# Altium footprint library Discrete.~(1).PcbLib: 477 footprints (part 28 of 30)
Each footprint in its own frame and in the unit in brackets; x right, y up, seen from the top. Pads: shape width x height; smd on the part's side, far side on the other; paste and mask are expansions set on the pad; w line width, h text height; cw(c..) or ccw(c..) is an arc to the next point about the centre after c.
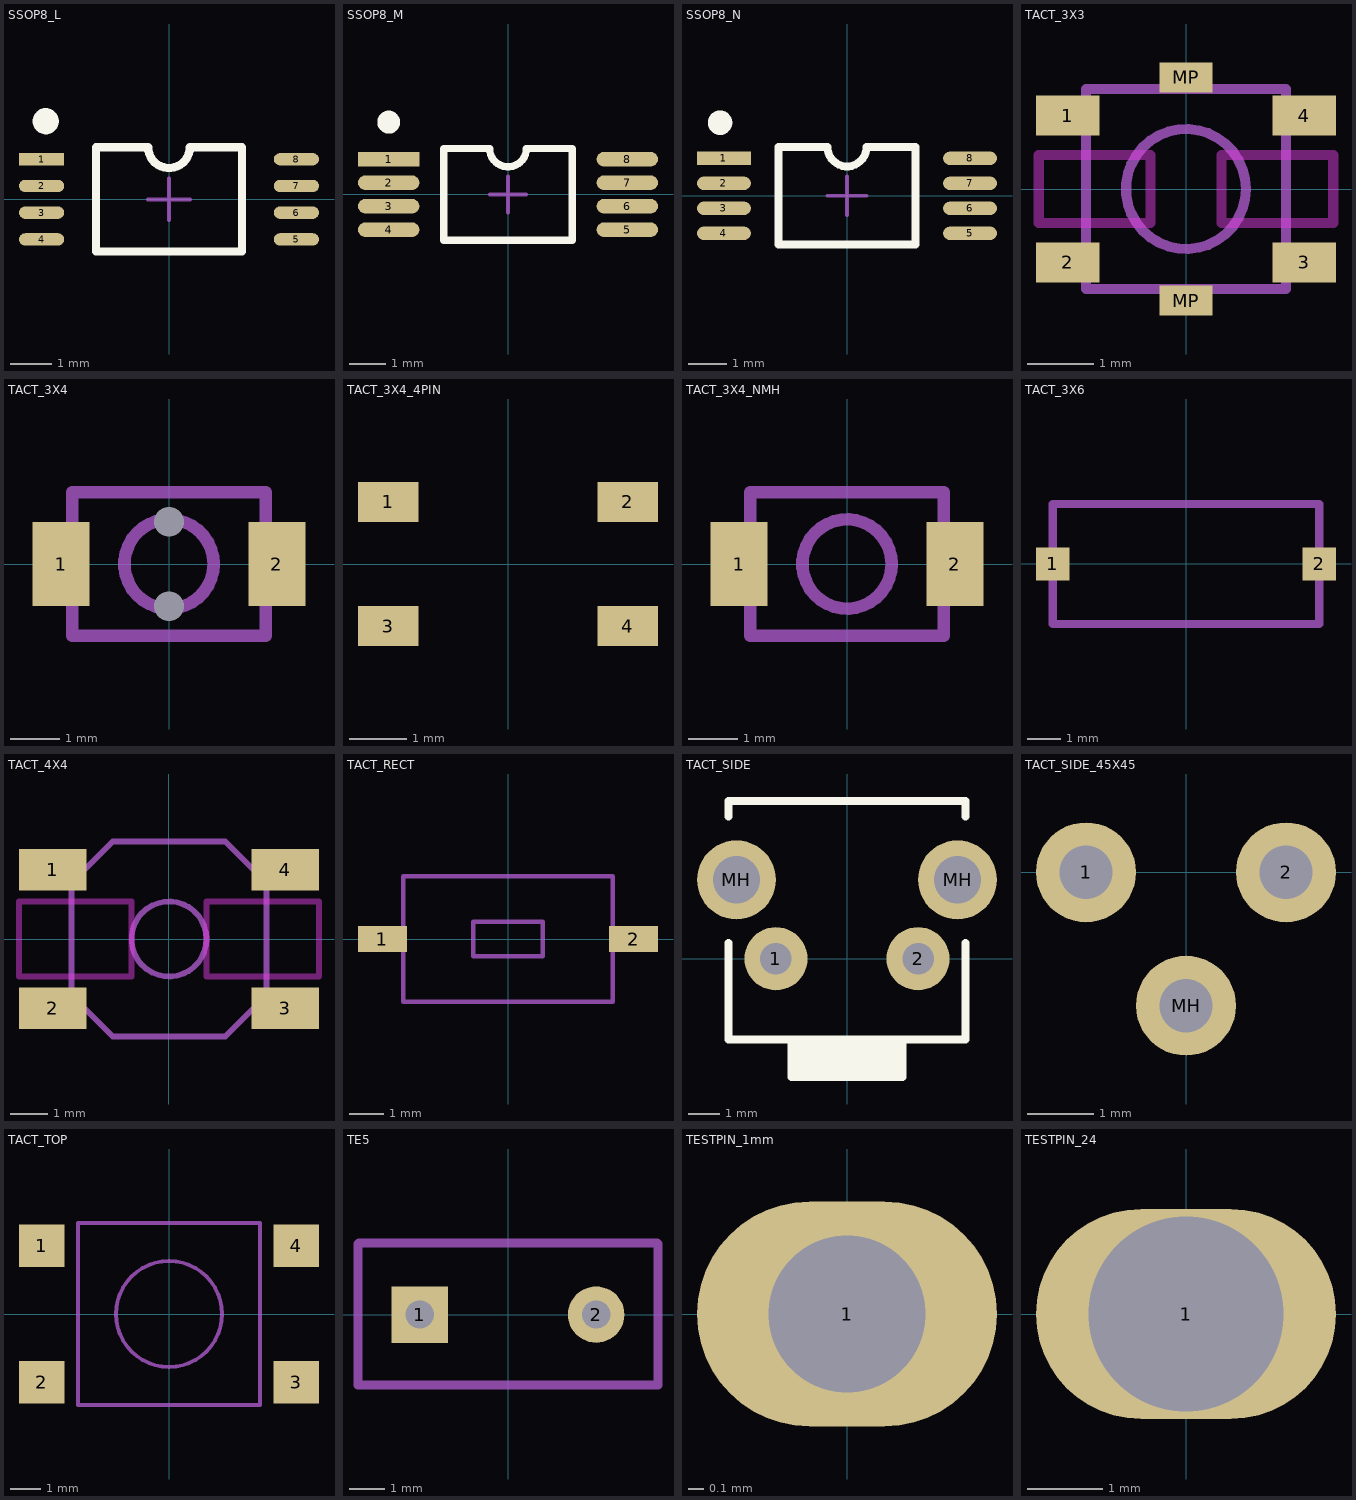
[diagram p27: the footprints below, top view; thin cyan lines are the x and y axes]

## SSOP8_L [mm] "3*6.4*1.2mm（长宽高）"
pads (8):
  rect 1.1x0.3 smd: 1(-3.1,0.975)
  oval 1.1x0.3 smd: 2(-3.1,0.325) 3(-3.1,-0.325) 4(-3.1,-0.975) 5(3.1,-0.975) 6(3.1,-0.325) 7(3.1,0.325) 8(3.1,0.975)
Top Overlay:
  circle w0.381: c-3,1.9 r0.127
  lines w0.203: -1.778,-1.27 -1.778,1.27 -0.508,1.27 ccw(c0,1.27) 0.508,1.27 1.778,1.27 1.778,-1.27 -1.778,-1.27
Mechanical 15:
  lines w0.1: -0.508,0 0.508,0 ; 0,-0.508 0,0.508
3D body "SSOP8.STEP": height 1.25, standoff -0.02, extent -3.203,-1.75 3.203,1.75

## SSOP8_M [mm] "3*6.4*1.2mm（长宽高）"
pads (8):
  rect 1.7x0.4 smd: 1(-3.3,0.975)
  oval 1.7x0.4 smd: 2(-3.3,0.325) 3(-3.3,-0.325) 4(-3.3,-0.975) 5(3.3,-0.975) 6(3.3,-0.325) 7(3.3,0.325) 8(3.3,0.975)
Top Overlay:
  circle w0.381: c-3.3,2 r0.127
  lines w0.203: -1.778,-1.27 -1.778,1.27 -0.508,1.27 ccw(c0,1.27) 0.508,1.27 1.778,1.27 1.778,-1.27 -1.778,-1.27
Mechanical 15:
  lines w0.1: -0.508,0 0.508,0 ; 0,-0.508 0,0.508
3D body "SSOP8.STEP": height 1.25, standoff -0.02, extent -3.203,-1.75 3.203,1.75

## SSOP8_N [mm] "3*6.4*1.2mm（长宽高）"
pads (8):
  rect 1.4x0.35 smd: 1(-3.2,0.975)
  oval 1.4x0.35 smd: 2(-3.2,0.325) 3(-3.2,-0.325) 4(-3.2,-0.975) 5(3.2,-0.975) 6(3.2,-0.325) 7(3.2,0.325) 8(3.2,0.975)
Top Overlay:
  circle w0.381: c-3.3,1.9 r0.127
  lines w0.203: -1.778,-1.27 1.778,-1.27 1.778,1.27 0.508,1.27 cw(c0,1.27) -0.508,1.27 -1.778,1.27 -1.778,-1.27
Mechanical 15:
  lines w0.1: -0.508,0 0.508,0 ; 0,-0.508 0,0.508
3D body "SSOP8.STEP": height 1.25, standoff -0.02, extent -3.203,-1.75 3.203,1.75

## TACT_3X3 [mm]
pads (6):
  rect 0.95x0.6 smd: 1(-1.775,1.1) 2(-1.775,-1.1) 3(1.775,-1.1) 4(1.775,1.1)
  rect 0.8x0.45 smd: MP(0,-1.675) MP(0,1.675)
Top Layer keep-out:
  lines w0.152: -2.21,-0.51 -0.533,-0.51 -0.533,0.51 -2.21,0.51 -2.21,-0.51 ; 0.533,-0.51 0.533,0.51 2.21,0.51 2.21,-0.51 0.533,-0.51
Mechanical 13:
  circle w0.152: c0,0 r0.9
  lines w0.152: -1.5,-1.5 1.5,-1.5 1.5,1.5 -1.5,1.5 -1.5,-1.5
3D body: height 1.1, standoff 0, extent -1.5,-1.5 1.5,1.5
3D body: height 1.5, standoff 0, extent -0.893,-0.898 0.9,0.898

## TACT_3X4 [mm]
pads (4):
  rect 1.15x1.7 smd: 1(-2.175,0) 2(2.175,0)
  round 0.1 hole 0.6 unplated: MH(0,-0.85) MH(0,0.85)
Mechanical 13:
  circle w0.254: c0,0 r0.9
  lines w0.254: -1.95,-1.45 1.95,-1.45 1.95,1.45 -1.95,1.45 -1.95,-1.45
3D body: height 2, standoff 1.5, extent -0.794,-0.798 0.8,0.798
3D body: height 1.5, standoff 0, extent -1.95,-1.45 1.95,1.45

## TACT_3X4_4PIN [mm]
pads (4):
  rect 1.05x0.7 smd: 1(-2.075,1.075) 2(2.075,1.075) 3(-2.075,-1.075) 4(2.075,-1.075)
3D body "SKRPADE010 v2.step": height 2.5, standoff 0, extent -2.3,-1.6 2.3,1.6

## TACT_3X4_NMH [mm]
pads (2):
  rect 1.15x1.7 smd: 1(-2.175,0) 2(2.175,0)
Mechanical 13:
  circle w0.254: c0,0 r0.9
  lines w0.254: -1.95,-1.45 -1.95,1.45 1.95,1.45 1.95,-1.45 -1.95,-1.45
3D body: height 1.5, standoff 0, extent -1.95,-1.45 1.95,1.45
3D body: height 2, standoff 1.5, extent -0.794,-0.798 0.8,0.798

## TACT_3X6 [mm]
pads (2):
  rect 1x1 smd: 1(-4,0) 2(4,0)
Mechanical 13:
  lines w0.254: -4,-1.8 4,-1.8 4,1.8 -4,1.8 -4,-1.8 ; -4,-1.8 -4,-1.8
3D body "User Library-Tact switch 1181_3.STEP": height 2.4, standoff -0.1, extent -4,-1.8 4,1.8

## TACT_4X4 [mm]
pads (4):
  rect 1.8x1.1 smd: 1(-3.1,1.85) 2(-3.1,-1.85) 3(3.1,-1.85) 4(3.1,1.85)
Top Layer keep-out:
  lines w0.152: -4,-1 -4,1 -1,1 -1,-1 -4,-1 ; 1,-1 1,1 4,1 4,-1 1,-1
Mechanical 13:
  circle w0.152: c0,0 r1
  lines w0.152: -2.6,-1.5 -2.6,1.5 -1.5,2.6 1.5,2.6 2.6,1.5 2.6,-1.5 1.5,-2.6 -1.5,-2.6 -2.6,-1.5
3D body "User Library-button1.STEP": height 1.4, standoff 0, extent -3.2,-2.65 3.203,2.65

## TACT_RECT [mm]
pads (2):
  rect 1.4x0.75 smd: 1(-3.6,0) 2(3.6,0)
Mechanical 13:
  lines w0.127: -3,-1.8 3,-1.8 3,1.8 -3,1.8 -3,-1.8 ; -1,-0.5 -1,0.5 1,0.5 1,-0.5 -1,-0.5
3D body: height 2.8, standoff 0, extent -1,-0.5 1,0.5
3D body: height 2.4, standoff 0, extent -3,-1.8 3,1.8

## TACT_SIDE [mm] "Tact Switch Side Push"
pads (4):
  round 2 hole 1: 1(-2.25,0) 2(2.25,0)
  round 2.5 hole 1.5: MH(-3.5,2.5) MH(3.5,2.5)
Top Overlay:
  rectangle: -1.75,-3.75 1.75,-2.55
  lines w0.254: -3.75,0.5 -3.75,-2.55 3.75,-2.55 3.75,0.5 ; -3.75,4.5 -3.75,5 3.75,5 3.75,4.5 ; -1.75,-2.55 -1.75,-3.75 1.75,-3.75 1.75,-2.55

## TACT_SIDE_45X45 [mm]
pads (3):
  round 1.5 hole 0.8: 1(-1.5,0) 2(1.5,0) MH(0,-2)

## TACT_TOP [mm] "Tact Switch Side Push"
pads (4):
  rect 1.5x1.4 smd mask+0: 1(-4.2,2.25) 2(-4.2,-2.25) 3(4.2,-2.25) 4(4.2,2.25)
Mechanical 13:
  circle w0.127: c0,0 r1.75
  lines w0.127: -3,-3 -3,0 -3,3 3,3 3,-3 -3,-3
3D body "TSW SMD-6x6x4.3.STEP": height 4.25, standoff 0.05, extent -4.5,-3 4.5,3

## TE5 [mm] "TE5 Time-Lag Fuse"
pads (2):
  rect 1.6x1.6 hole 0.8: 1(-2.5,0)
  round 1.6 hole 0.8: 2(2.5,0)
Mechanical 13:
  lines w0.254: -4.25,-2 4.25,-2 4.25,2 4.218,2.032 -4.218,2.032 -4.25,2 -4.25,-2
3D body "User Library-A3D-008-00001.STEP": height 8, standoff -3, extent -4.25,-2 4.25,2

## TESTPIN_1mm [mm]
pads (1):
  oval 2x1.5 hole 1.05: 1(0,0)

## TESTPIN_24 [mm]
pads (1):
  oval 4x2.8 hole 2.6: 1(0,0)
